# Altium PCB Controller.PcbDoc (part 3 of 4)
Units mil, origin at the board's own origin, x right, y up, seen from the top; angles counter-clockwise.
Board outline 5000 x 8750 mil, 6 copper layers (Top Layer, Layer 1, Layer 2, Layer 3, Layer 4, Bottom Layer), stack 92.6 mil thick; 303 components, 258 nets, 1062 pads, 274 vias.
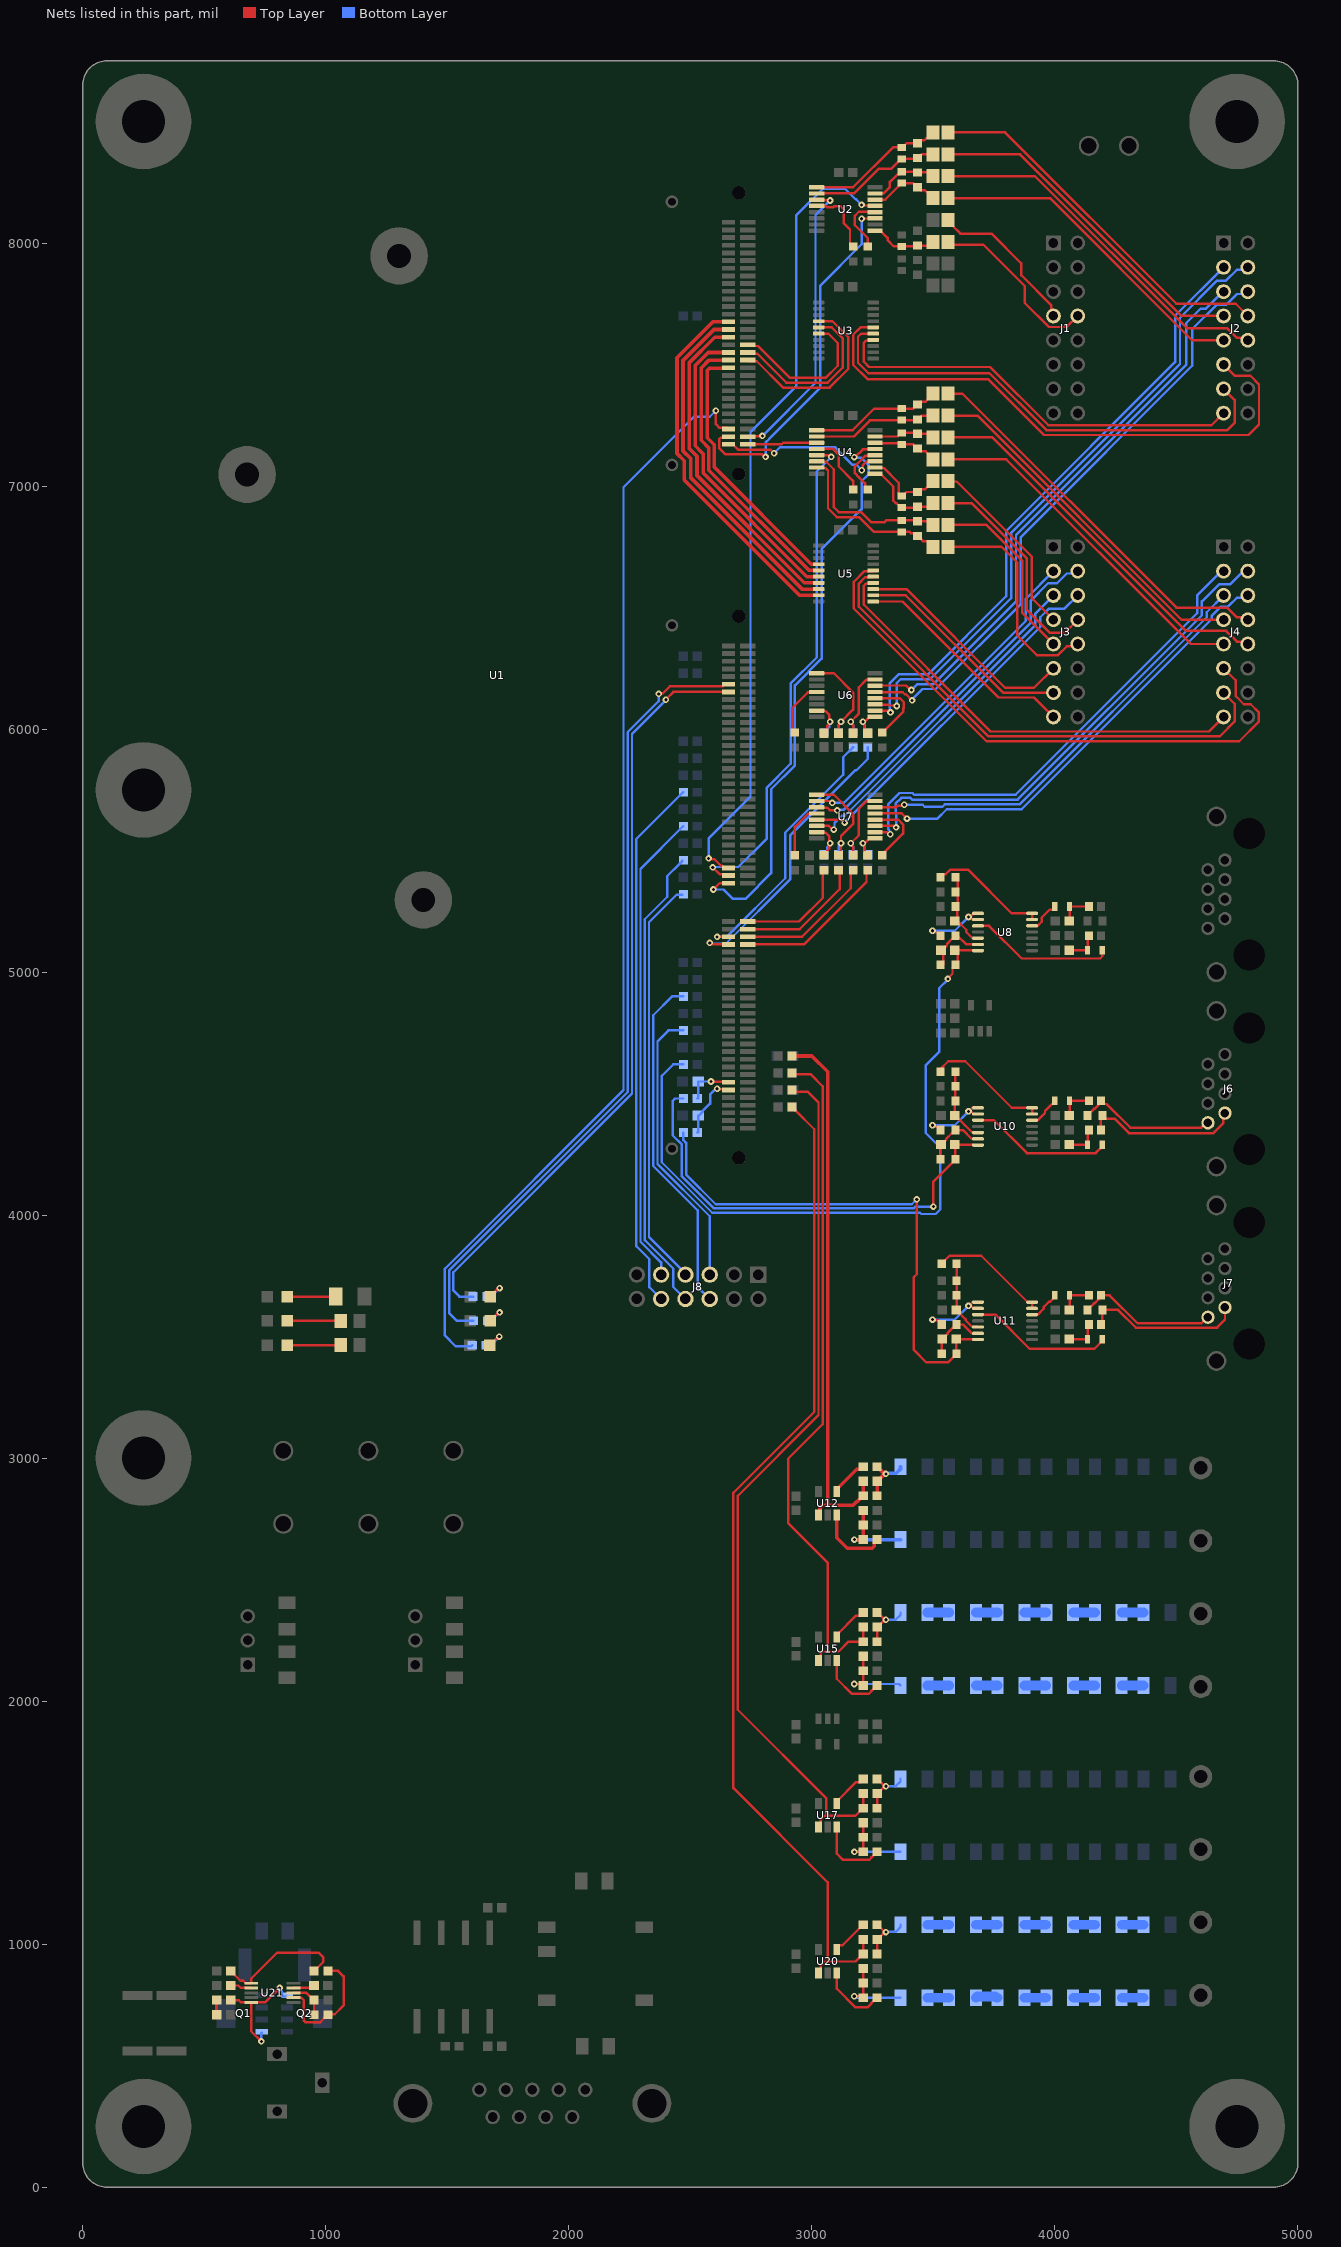
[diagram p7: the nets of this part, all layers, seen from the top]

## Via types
v1: diameter 27, hole 13, Top Layer to Bottom Layer, tented both sides, 274 vias

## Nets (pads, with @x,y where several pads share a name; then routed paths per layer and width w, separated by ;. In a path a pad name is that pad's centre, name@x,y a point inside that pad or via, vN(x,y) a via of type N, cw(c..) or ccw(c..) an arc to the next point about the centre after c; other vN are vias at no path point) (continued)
I_IN: C84.1 R95.2 U1.12 | length 268.7
  Top Layer w10: v1(2610,4520) 2612.32,4517.68 2655.35,4517.68 U1.12@2657.68,4515.35
  Bottom Layer w10: R95.2@2528.62,4340 ccw(c2528.62,4343.93) 2532.55,4343.93 C84.1@2532.55,4410 2535.43,4410 2550.36,4424.92 2550.36,4427.81 2581.5,4458.95 2581.5,4496.81 2601.44,4516.75 2606.75,4516.75 v1(2610,4520)
I_IN_N: J7.7 R51.2 R53.1 | length 660.5
  Top Layer w10: R53.1@4189.63,3550 4195.58,3555.95 R51.2@4195.58,3610 4260,3610 4332.68,3537.32 4667.32,3537.32 4700,3570 J7.7@4700,3620
I_IN_P: J7.8 R48.1 R51.1 | length 582.8
  Top Layer w10: R51.1@4134.42,3610 4134.42,3611.05 4160.47,3637.1 4163.35,3637.1 4177.8,3651.55 4177.8,3658.17 R48.1@4189.63,3670 4225,3670 4340,3555 4602.92,3555 4627.76,3579.84 J7.8@4629.92,3579.84
I_OUT: C81.1 R94.2 U1.14 | length 198.7
  Top Layer w10: v1(2585,4550) 2586.5,4548.5 2656.03,4548.5 U1.14@2657.68,4546.85
  Bottom Layer w10: R94.2@2528.62,4480 ccw(c2528.62,4483.93) 2532.55,4483.93 C81.1@2532.55,4550 v1(2585,4550)
I_OUT_N: J6.7 R40.2 R41.1 | length 652.4
  Top Layer w10: R41.1@4189.63,4350 4189.63,4404.05 R40.2@4195.58,4410 4195.58,4408.95 4207.48,4397.04 4244.67,4397.04 4304.39,4337.32 4652.32,4337.32 4692.48,4377.48 4692.48,4412.48 J6.7@4700,4420
I_OUT_P: J6.8 R36.1 R40.1 | length 579.2
  Top Layer w10: R40.1@4134.42,4410 4134.42,4411.05 4160.47,4437.1 4163.35,4437.1 4177.8,4451.55 4177.8,4458.17 R36.1@4189.63,4470 4189.63,4469.07 4201.46,4457.24 4212.76,4457.24 4310,4360 4601.54,4360 4621.39,4379.84 J6.8@4629.92,4379.84
INA_FLT: U1.121 U4.3 | length 286.2
  Top Layer w10: U1.121@2736.42,7171.78 2876.22,7171.78 2882.83,7178.39 U4.3@3019.92,7178.39
INA_FLT_N: J4.8 L9.1 | length 1618.8
  Top Layer w10: L9.1@3560.55,7380 3620,7380 4500.07,6499.93 4708.53,6499.93 4748.69,6459.76 4784.33,6459.76 J4.8@4794.09,6450
INA_FLT_N_FILT: C7.2 L9.2 R7.1 U4.1 | length 543
  Top Layer w10: U4.1@3019.92,7229.57 3168.03,7229.57 3257.09,7318.62 C7.2@3370,7318.62 3416.99,7318.62 3433.95,7335.58 R7.1@3435,7335.58 3435.58,7335.58 3447.48,7347.48 3468.94,7347.48 3499.45,7378 L9.2@3499.45,7380
INA_FLT_P: J4.7 L10.1 | length 1481.5
  Top Layer w10: L10.1@3560.55,7290 3681.72,7290 4521.72,6450 J4.7@4694.09,6450
INA_FLT_P_FILT: C7.1 L10.2 R7.2 U4.2 | length 515.2
  Top Layer w10: U4.2@3019.92,7203.98 3173.03,7203.98 3239.06,7270 3365.67,7270 3367.05,7271.38 3431.96,7271.38 R7.2@3435,7274.42 3436.05,7274.42 3451.63,7290 L10.2@3499.45,7290
INA_HS: R19.1 U1.49 | length 643.5
  Top Layer w10: U1.49@2736.42,5113.78 2967.69,5113.78 3225,5371.09 R19.1@3225,5419.42
INA_HS_N: J4.4 U7.3 | length 2072.5
  Top Layer w10: U7.3@3260.08,5601.61 3336.16,5601.61 3342.23,5595.54 v1(3346.83,5595.54)
  Bottom Layer w10: v1(3346.83,5595.54) 3346.83,5653.17 3345,5655 3345,5693.5 3368.5,5717 3405.82,5717 3412.82,5710 3846.74,5710 4605,6468.26 4605,6525.27 4675.24,6595.51 4720.51,6595.51 4765.24,6640.24 4784.33,6640.24 J4.4@4794.09,6650
INA_HS_P: J4.3 U7.2 | length 2001.9
  Top Layer w10: U7.2@3260.08,5576.02 3309.58,5576.02
  Bottom Layer w10: v1(3322.79,5567.42) 3319.54,5570.67 3319.54,5582.53 3315,5587.07 3315,5691.78 3360.22,5737 3414.11,5737 3421.11,5730 3838.46,5730 3996.53,5888.07 4585,6476.54 4585,6550 4685,6650 J4.3@4694.09,6650
INA_LEN: J4.13 U5.15 | length 2095.5
  Top Layer w10: U5.15@3252.2,6627.2 3249.49,6624.49 3219.49,6624.49 3193.58,6598.58 3193.58,6503.62 3727.21,5970 4678.46,5970 4739.61,6031.15 4739.61,6104.49 J4.13@4694.09,6150
INA_LEN_CTRL: U1.144 U5.5 | length 1182.2
  Top Layer w15: U1.144@2657.68,7518.24 2577.27,7518.24 2545,7485.97 2545,7187.94 2576.1,7156.83 2576.1,7065.22 2988.31,6653.01 3027.58,6653.01 U5.5@3027.8,6652.8
INA_LS: R18.1 U1.51 | length 589.7
  Top Layer w10: U1.51@2736.42,5145.28 2960,5145.28 3160,5345.28 3160,5414.42 R18.1@3170,5424.42
INA_LS_N: J4.6 U7.5 | length 1931.2
  Top Layer w10: U7.5@3260.08,5652.8 3370.19,5652.8 v1(3391.48,5631.5)
  Bottom Layer w10: v1(3391.48,5631.5) 3516.5,5631.5 3555,5670 3863.31,5670 4645,6451.69 4645,6465.27 4684.22,6504.49 4712.95,6504.49 4748.69,6540.24 4784.33,6540.24 J4.6@4794.09,6550
INA_LS_P: J4.5 U7.6 | length 1814.4
  Top Layer w10: U7.6@3260.08,5678.39 3260.89,5679.19 3346.8,5679.19 3352.86,5685.25 3377.05,5685.25 v1(3380.31,5688.5)
  Bottom Layer w10: v1(3380.31,5688.5) 3456.56,5688.5 3465.06,5680 3536.72,5680 3546.72,5690 3855.03,5690 4625,6459.97 4625,6480.91 J4.5@4694.09,6550
INA_NTC: U1.58 U4.13 | length 2389.3
  Top Layer w10: v1(2595,5340) 2620.75,5365.75 U1.58@2657.68,5365.75 ; v1(3174.4,7119.36) 3178.31,7119.36 3210.01,7151.06 3258.35,7151.06 U4.13@3260.08,7152.8
  Bottom Layer w10: v1(2595,5340) 2636.45,5340 2674.95,5301.5 2726.5,5301.5 2832.5,5407.5 2832.5,5752.5 2930,5850 2930,6180 3040,6290 3040,6740.31 3205,6905.31 3205,7020 3235,7050 3235,7085 3202.9,7117.1 3176.66,7117.1 v1(3174.4,7119.36)
INA_NTC_N: J4.10 L11.1 | length 1585.6
  Top Layer w10: L11.1@3560.55,7200 3743.43,7200 4539.6,6403.83 4704.62,6403.83 4748.69,6359.76 4784.33,6359.76 J4.10@4794.09,6350
INA_NTC_N_FILT: C9.2 L11.2 R8.1 U4.15 | length 253.2
  Top Layer w10: U4.15@3260.08,7203.98 3352.4,7203.98 3367.05,7218.62 C9.2@3370,7218.62 3431.96,7218.62 R8.1@3435,7215.58 3483.87,7215.58 L11.2@3499.45,7200
INA_NTC_P: J4.9 L12.1 | length 1448.4
  Top Layer w10: L12.1@3560.55,7110 3800,7110 4560,6350 J4.9@4694.09,6350
INA_NTC_P_FILT: C9.1 L12.2 R8.2 U4.14 | length 268.9
  Top Layer w10: U4.14@3260.08,7178.39 3261.81,7176.65 3364.72,7176.65 C9.1@3370,7171.38 3416.99,7171.38 3433.95,7154.42 R8.2@3435,7154.42 3446.9,7142.52 3468.94,7142.52 3499.45,7112 L12.2@3499.45,7110
INA_OCEN: J4.15 U5.14 | length 1842.5
  Top Layer w10: U5.14@3252.2,6601.61 3249.49,6598.9 3223.52,6598.9 3213.58,6588.96 3213.58,6511.91 3735.49,5990 4634.09,5990 J4.15@4694.09,6050
INA_OCEN_CTRL: U1.146 U5.6 | length 1268
  Top Layer w15: U1.146@2657.68,7549.73 2573.41,7549.73 2520,7496.32 2520,7166.01 2545.5,7140.5 2545.5,7139.85 2552.5,7132.86 2552.5,7082.76 2552.63,7082.63 2552.63,7053.34 2978.76,6627.2 U5.6@3027.8,6627.2
INA_PSDIS: J4.11 U5.16 | length 2431.5
  Top Layer w10: U5.16@3252.2,6652.8 3249.49,6650.08 3216.79,6650.08 3172.5,6605.78 3172.5,6496.42 3718.92,5950 4758.46,5950 4839.61,6031.15 4839.61,6068.85 4806.19,6102.27 4777.46,6102.27 4744.04,6135.69 4744.04,6200.06 J4.11@4694.09,6250
INA_PSDIS_CTRL: U1.142 U5.4 | length 1096.4
  Top Layer w15: U1.142@2657.68,7486.74 2655.33,7484.4 2578.79,7484.4 2570,7475.61 2570,7198.29 2598.6,7169.69 2598.6,7078.08 2998.08,6678.6 3027.58,6678.6 U5.4@3027.8,6678.39
INB_FLT: U1.122 U4.11 | length 693.3
  Top Layer w10: U1.122@2657.68,7171.78 2674.41,7171.78 2696.19,7150 2698.2,7150 2698.76,7149.44 2830.56,7149.44 v1(2845,7135) ; v1(3205.4,7065.1) 3208.65,7068.35 3208.65,7085.03 3223.51,7099.88 3258.35,7099.88 U4.11@3260.08,7101.61
  Bottom Layer w10: v1(2845,7135) 2870,7160 3095.31,7160 3107.44,7147.86 3107.44,7146.01 3165.5,7087.95 3182.55,7087.95 v1(3205.4,7065.1)
INB_FLT_N: J3.8 L14.1 | length 901.2
  Top Layer w10: L14.1@3560.55,6930 3656.72,6930 3885,6701.72 3885,6490.51 3980,6395.51 4039.61,6395.51 J3.8@4094.09,6450
INB_FLT_N_FILT: C10.2 L14.2 R11.1 U4.9 | length 338.8
  Top Layer w10: U4.9@3260.08,7050.43 3282.72,7050.43 3335,6998.15 3335,6939.93 3346.07,6928.86 3349.57,6928.86 3367.05,6911.38 C10.2@3370,6911.38 3431.96,6911.38 R11.1@3435,6914.42 3483.87,6914.42 L14.2@3499.45,6930
INB_FLT_P: J3.7 L13.1 | length 769.8
  Top Layer w10: L13.1@3560.55,7020 3561.9,7018.65 3596.35,7018.65 3905,6710 3905,6539.09 J3.7@3994.09,6450
INB_FLT_P_FILT: C10.1 L13.2 R11.2 U4.10 | length 341.1
  Top Layer w10: U4.10@3260.08,7076.02 3261.81,7074.29 3296.65,7074.29 3357.28,7013.65 3357.28,6968.39 3367.05,6958.62 C10.1@3370,6958.62 3372.95,6958.62 3389.91,6975.58 R11.2@3435,6975.58 3446.9,6987.48 3466.94,6987.48 3475.79,6996.33 3477.79,6996.33 3499.45,7018 L13.2@3499.45,7020
INB_HS: R17.1 U1.53 | length 531.6
  Top Layer w10: U1.53@2736.42,5176.77 2950,5176.77 3115,5341.77 3115,5419.42 R17.1@3110,5424.42
INB_HS_N: J3.4 U7.11 | length 1540.8
  Top Layer w10: U7.11@3019.92,5678.39 3021.65,5676.65 3063.4,5676.65 3074.79,5665.26 v1(3104.78,5665.26)
  Bottom Layer w10: v1(3104.78,5665.26) 3108.04,5668.51 3131.94,5668.51 3900,6436.57 3900,6527.62 3972.38,6600 4008.46,6600 4048.69,6640.24 4084.33,6640.24 J3.4@4094.09,6650
INB_HS_P: J3.3 U7.10 | length 1425.9
  Top Layer w10: U7.10@3019.92,5703.98 3071.78,5703.98 3079.69,5696.06 v1(3084.29,5696.06)
  Bottom Layer w10: v1(3084.29,5696.06) 3131.21,5696.06 3880,6444.85 3880,6535.91 J3.3@3994.09,6650
INB_LEN: J3.13 U5.12 | length 907.8
  Top Layer w10: U5.12@3252.2,6550.43 3386.14,6550.43 3786.57,6150 J3.13@3994.09,6150
INB_LEN_CTRL: U1.152 U5.8 | length 1452.6
  Top Layer w15: U1.152@2657.68,7644.22 2597.19,7644.22 2470,7517.03 2470,7144.64 2502.32,7112.32 2502.32,7032.94 2959.24,6576.02 U5.8@3027.8,6576.02
INB_LS: R16.1 U1.55 | length 469.9
  Top Layer w10: U1.55@2736.42,5208.27 2947.8,5208.27 3045,5305.47 3045,5419.42 R16.1@3050,5424.42
INB_LS_N: J3.6 U7.13 | length 1490.1
  Top Layer w10: U7.13@3019.92,5627.2 3118.19,5627.2 3130.4,5615 v1(3135,5615)
  Bottom Layer w10: v1(3135,5615) 3940,6420 3940,6460.27 3975.24,6495.51 4039.61,6495.51 J3.6@4094.09,6550
INB_LS_P: J3.5 U7.14 | length 1421.4
  Top Layer w10: U7.14@3019.92,5601.61 3070.29,5601.61 3085.4,5586.5 v1(3090,5586.5)
  Bottom Layer w10: v1(3090,5586.5) 3093.25,5589.75 3093.25,5613.56 3123.19,5643.5 3135.22,5643.5 3920,6428.28 3920,6475 3994.09,6549.09 J3.5@3994.09,6550
INB_NTC: U1.60 U4.5 | length 2093.9
  Top Layer w10: v1(2592.45,5431) 2621.37,5402.09 2652.83,5402.09 U1.60@2657.68,5397.24 ; U4.5@3019.92,7127.2 3068.2,7127.2 3075.4,7120 v1(3080,7120)
  Bottom Layer w10: v1(2592.45,5431) 2593.93,5432.48 2697.48,5432.48 2815,5550 2815,5759.75 2912.5,5857.25 2912.5,6187.5 3020,6295 3020,7060 v1(3080,7120)
INB_NTC_N: J3.10 L16.1 | length 912.8
  Top Layer w10: L16.1@3560.55,6750 3780.15,6750 3845,6685.15 3845,6385 3925.51,6304.49 4012.95,6304.49 4048.69,6340.24 4084.33,6340.24 J3.10@4094.09,6350
INB_NTC_N_FILT: C11.2 L16.2 R12.1 U4.7 | length 707
  Top Layer w10: U4.7@3019.92,7076.02 3021.65,7074.29 3056.49,7074.29 3066.42,7064.36 3066.42,6908.58 3102.48,6872.52 3194.2,6872.52 3255.34,6811.38 C11.2@3370,6811.38 3402.72,6811.38 3407.77,6806.32 3423.1,6806.32 R12.1@3435,6794.42 3436.05,6794.42 3456.81,6773.67 3477.79,6773.67 3499.45,6752 L16.2@3499.45,6750
INB_NTC_P: J3.9 L15.1 | length 762.1
  Top Layer w10: L15.1@3560.55,6840 3718.43,6840 3865,6693.43 3865,6479.09 J3.9@3994.09,6350
INB_NTC_P_FILT: C11.1 L15.2 R12.2 U4.6 | length 685.1
  Top Layer w10: U4.6@3019.92,7101.61 3021.65,7099.88 3059.18,7099.88 3090,7069.06 3090,6913.28 3110.77,6892.52 3202.48,6892.52 3243.5,6851.5 3299.18,6851.5 3306.3,6858.62 3431.96,6858.62 R12.2@3435,6855.58 3483.87,6855.58 L15.2@3499.45,6840
INB_OCEN: J3.15 U5.11 | length 938.6
  Top Layer w10: U5.11@3252.2,6524.84 3372.95,6524.84 3767.8,6130 3914.09,6130 J3.15@3994.09,6050
INB_OCEN_CTRL: U1.154 U5.9 | length 1538.4
  Top Layer w15: U1.154@2657.68,7675.72 2593.33,7675.72 2445,7527.39 2445,7134.29 2474.64,7104.64 2474.64,7025.26 2949.47,6550.43 U5.9@3027.8,6550.43
INB_PSDIS: J3.11 U5.13 | length 943.2
  Top Layer w10: U5.13@3252.2,6576.02 3388.83,6576.02 3794.85,6170 3914.09,6170 J3.11@3994.09,6250
INB_PSDIS_CTRL: U1.150 U5.7 | length 1366.8
  Top Layer w15: U1.150@2657.68,7612.72 2601.05,7612.72 2495,7506.68 2495,7155 2527.5,7122.5 2527.5,7043.11 2969,6601.61 U5.7@3027.8,6601.61
LED_G: R96.2 U1.108 | length 3157.3
  Top Layer w10: v1(2399.68,6120.57) 2399.68,6122.68 2430.16,6153.15 U1.108@2657.68,6153.15
  Bottom Layer w10: R96.2@1606.38,3665 1550,3665 1525,3690 1525,3765 2260,4500 2260,5980 2399.68,6119.68 v1(2399.68,6120.57)
LED_R: R98.2 U1.126 | length 4554.5
  Top Layer w10: v1(2605,7310) 2605,7255 2620.39,7239.61 2652.83,7239.61 U1.126@2657.68,7234.77
  Bottom Layer w10: R98.2@1602.76,3465 1597.76,3460 1535,3460 1490,3505 1490,3779.5 2225,4514.5 2225,6995.13 2514.87,7285 2580,7285 v1(2605,7310)
LED_Y: R97.2 U1.110 | length 3322.6
  Top Layer w10: v1(2370,6145) 2372.65,6147.65 2387.65,6147.65 2415.49,6175.49 2631.79,6175.49 2640.94,6184.65 U1.110@2657.68,6184.65
  Bottom Layer w10: R97.2@1607.76,3565 1540,3565 1507.5,3597.5 1507.5,3772.25 2242.5,4507.25 2242.5,5987.5 2370,6115 v1(2370,6145)
NetC14_1: C14.1 R86.2 U6.15 | length 201.4
  Top Layer w10: U6.15@3019.92,6076.02 3021.65,6074.29 3056.49,6074.29 3072.28,6058.5 3072.28,6032.72 v1(3075,6030) 3075,6025.4 3063.86,6014.26 3063.86,5997.44 C14.1@3050,5983.58
  Bottom Layer w10: R86.2@3050,5985.58 3051.05,5985.58 3062.96,5997.48 3062.96,5998.53 3071.75,6007.33 3071.75,6026.75 v1(3075,6030)
NetC15_1: C15.1 R85.2 U6.9 | length 423.3
  Top Layer w10: U6.9@3019.92,6229.57 3091.09,6229.57 3170,6150.66 3170,6080 v1(3120,6030) 3120,6026.29 3110,6016.29 C15.1@3110,5983.58
  Bottom Layer w10: R85.2@3110,5985.58 3110,6016.29 3120,6026.29 v1(3120,6030)
NetC16_1: C16.1 R84.2 U6.7 | length 334.5
  Top Layer w10: v1@3160,6030 3193.38,6063.38 3193.38,6172.11 3223.51,6202.24 3258.35,6202.24 U6.7@3260.08,6203.98 ; v1(3160.15,6029.85) 3160.15,6026.14 3170,6016.29 C16.1@3170,5983.58
  Bottom Layer w10: v1(3160.15,6029.85) 3160.15,6026.14 3170,6016.29 R84.2@3170,5985.58
NetC17_1: C17.1 R83.2 U6.1 | length 152
  Top Layer w10: C17.1@3230,5983.58 3216.14,5997.44 3216.14,6019.26 3210,6025.4 v1(3210,6030) 3213.25,6033.25 3220.26,6033.25 3237.44,6050.43 U6.1@3260.08,6050.43
  Bottom Layer w10: 3217.04,6018.36 3217.04,5997.48 3228.95,5985.58 R83.2@3230,5985.58
NetC19_1: C19.1 R21.2 R22.1 R24.2 U8.12 | length 300.8
  Top Layer w10: R21.2@3600.58,5390 3600.58,5330 3600.58,5270 3598.58,5268 3598.58,5210 3599.53,5210 3635.19,5174.33 3635.19,5164.91 3659.97,5140.13 3683.06,5140.13 U8.12@3683.78,5139.41
NetC20_1: C20.1 R23.2 R25.1 | length 140.7
  Top Layer w10: C20.1@4058.58,5210 4060.51,5211.93 R25.1@4060.51,5270 R23.2@4140.37,5270
NetC22_1: C22.1 R28.2 R30.1 U8.13 | length 251.3
  Top Layer w10: R30.1@3539.42,5030 3541.42,5032 3541.42,5099.05 3546.24,5103.86 3550.41,5103.86 3556.26,5109.72 3556.26,5116.26 3577.04,5137.04 3588.68,5137.04 3600.58,5148.95 3635.71,5113.82 U8.13@3683.78,5113.82
NetC22_2: C22.2 R30.2 R93.1 U8.14 | length 2934.9
  Top Layer w10: v1(3560.08,4972.32) 3560.08,4974.68 3578.68,4993.28 3578.68,5018.1 R30.2@3590.58,5030 ; R30.2@3600.58,5030 3600.58,5088 3598.58,5090 3663.27,5090 3665.04,5088.23 U8.14@3683.78,5088.23
  Bottom Layer w10: R93.1@2471.38,4620 2429.69,4620 2382.5,4572.81 2382.5,4217.5 2590,4010 3445,4010 3450.25,4004.75 3510.06,4004.75 3528.5,4023.19 3528.5,4278.4 3468,4338.9 3468,4615.8 3523.5,4671.3 3523.5,4933.5 3560.08,4970.08 v1(3560.08,4972.32)
NetC23_1: C23.1 R27.2 R29.1 | length 138.3
  Top Layer w10: C23.1@4058.58,5090 R29.1@4134.49,5090 4134.49,5144.12 R27.2@4140.37,5150
NetC27_1: C27.1 R33.2 R34.1 R37.2 U10.12 | length 315.3
  Top Layer w10: R33.2@3590.58,4600 R34.1@3590.58,4530 R37.2@3590.58,4470 3588.58,4468 C27.1@3588.58,4410 3589.53,4410 3629.53,4370 3630.11,4370 3659.97,4340.13 3683.06,4340.13 U10.12@3683.78,4339.41
NetC28_1: C28.1 R36.2 R38.1 | length 140.7
  Top Layer w10: C28.1@4058.58,4410 4060.51,4411.93 R38.1@4060.51,4470 R36.2@4140.37,4470
NetC30_1: C30.1 R42.2 R44.1 U10.13 | length 255.8
  Top Layer w10: R44.1@3529.42,4230 3529.42,4288 C30.1@3531.42,4290 3532.37,4290 3553.76,4311.39 3553.76,4315.08 3575.73,4337.04 3578.68,4337.04 3590.58,4348.95 R42.2@3590.58,4350 3621.82,4350 3657.28,4314.54 3683.06,4314.54 U10.13@3683.78,4313.82
NetC30_2: C30.2 R44.2 R94.1 U10.14 | length 1856
  Top Layer w10: v1(3500,4035) 3500,4138.37 3590.58,4228.95 3590.58,4288 C30.2@3588.58,4290 3663.27,4290 3665.04,4288.23 U10.14@3683.78,4288.23
  Bottom Layer w10: R94.1@2471.38,4480 2437.52,4480 2427.5,4469.98 2427.5,4328.04 2465.35,4290.19 2465.35,4159.39 2597.25,4027.5 3418.44,4027.5 3425.94,4035 v1(3500,4035)
NetC31_1: C31.1 R41.2 R43.1 | length 138.3
  Top Layer w10: C31.1@4058.58,4290 R43.1@4134.49,4290 4134.49,4344.12 R41.2@4140.37,4350
NetC32_1: C32.1 R45.2 R46.1 R49.2 U11.12 | length 312.9
  Top Layer w10: R45.2@3595.58,3800 R46.1@3595.58,3730 R49.2@3595.58,3670 3595.58,3612 C32.1@3593.58,3610 3594.53,3610 3632.69,3571.83 3632.69,3567.41 3659.97,3540.13 3683.06,3540.13 U11.12@3683.78,3539.41
NetC33_1: C33.1 R48.2 R50.1 | length 140.7
  Top Layer w10: C33.1@4058.58,3610 4060.51,3611.93 R50.1@4060.51,3670 R48.2@4140.37,3670
NetC35_1: C35.1 R54.2 R57.1 U11.13 | length 250.8
  Top Layer w10: R57.1@3534.42,3430 3534.42,3488 C35.1@3536.42,3490 3537.37,3490 3558.76,3511.39 3558.76,3515.08 3580.73,3537.04 3583.68,3537.04 3595.58,3548.95 R54.2@3595.58,3550 3621.82,3550 3657.28,3514.54 3683.06,3514.54 U11.13@3683.78,3513.82
NetC35_2: C35.2 R57.2 R95.1 U11.14 | length 2174.1
  Top Layer w10: v1(3431.5,4065) 3431.5,3756.7 3420,3745.2 3420,3445 3470.86,3394.14 3560.77,3394.14 3595.58,3428.95 R57.2@3595.58,3430 3593.58,3432 C35.2@3593.58,3490 3663.27,3490 3665.04,3488.23 U11.14@3683.78,3488.23
  Bottom Layer w10: R95.1@2471.38,4340 2471.38,4308.91 2482.85,4297.44 2482.85,4166.64 2604.5,4045 3411.19,4045 3431.19,4065 v1(3431.5,4065)
NetC36_1: C36.1 R53.2 R55.1 | length 138.3
  Top Layer w10: C36.1@4058.58,3490 R55.1@4134.49,3490 4134.49,3544.12 R53.2@4140.37,3550
NetC37_1: C37.1 R58.1 R59.1 R104.2 | length 235.7
  Top Layer w15: R59.1@3268.62,2845 C37.1@3268.58,2905 3269.51,2904.98 3297.23,2932.7 3302.7,2932.7 v1(3305,2935) 3302,2935 3295.64,2941.36 3293.16,2941.36 3269.53,2965 R58.1@3268.62,2965
  Bottom Layer w15: v1(3305,2935) 3307.3,2937.3 3337.18,2937.3 3337.93,2938.05 3347.78,2938.05 3364.88,2955.16 R104.2@3364.88,2965
NetC37_2: C37.2 R31.1 R59.2 U12.1 | length 2246.5
  Top Layer w15: R31.1@2918.62,4655 3000,4655 3065,4590 3065,2806.91 ; U12.1@3027.6,2766.77 3033.72,2772.89 3033.72,2796.66 3043.97,2806.91 3065,2806.91 ; C37.2@3211.42,2905 R59.2@3211.38,2845 3210.47,2845 3186.84,2821.36 3184.36,2821.36 3169.91,2806.91 3065,2806.91
NetC39_1: C39.1 R60.2 R61.1 R110.2 | length 346.3
  Top Layer w15: v1(3175,2665) R61.1@3211.38,2665 R60.2@3211.38,2725 C39.1@3211.42,2785
  Bottom Layer w15: v1(3175,2665) R110.2@3364.88,2665
NetC42_1: C42.1 R62.1 R63.2 R116.2 | length 235.7
  Top Layer w10: R63.2@3268.62,2245 R63.2@3268.62,2245 C42.1@3268.58,2305 3269.53,2305 3296.27,2331.75 3301.75,2331.75 v1(3305,2335) 3301.75,2338.25 3296.27,2338.25 3269.53,2365 R62.1@3268.62,2365
  Bottom Layer w10: v1(3305,2335) 3305.55,2335.55 3345.28,2335.55 3364.88,2355.16 R116.2@3364.88,2365
NetC42_2: C42.2 R32.1 R63.1 U15.1 | length 2889.1
  Top Layer w10: R32.1@2918.62,4585 2923.62,4580 2995,4580 3045,4530 3045,3140 2902.5,2997.5 2902.5,2732.5 3065,2570 3065,2204.41 ; U15.1@3027.6,2166.77 3036.22,2175.39 3036.22,2195.62 3045.01,2204.41 3065,2204.41 ; C42.2@3211.42,2305 C42.2@3211.42,2305 R63.1@3211.38,2245 3151.55,2245 3110.96,2204.41 3065,2204.41
NetC46_1: C46.1 R64.1 R65.1 R122.2 | length 352.4
  Top Layer w10: v1(3174.35,2070.84) 3205.54,2070.84 R65.1@3211.38,2065 R64.1@3211.38,2125 R64.1@3211.38,2125 C46.1@3211.42,2185
  Bottom Layer w10: v1(3174.35,2070.84) 3359.04,2070.84 R122.2@3364.88,2065
NetC50_1: C50.1 R66.1 R67.1 R128.2 | length 235.7
  Top Layer w10: R67.1@3268.62,1560 R67.1@3268.62,1560 C50.1@3268.58,1620 3269.53,1620 3296.27,1646.75 3301.75,1646.75 v1(3305,1650) 3301.75,1653.25 3296.27,1653.25 3269.53,1680 R66.1@3268.62,1680
  Bottom Layer w10: v1(3305,1650) 3305.55,1650.55 3345.28,1650.55 3364.88,1670.16 R128.2@3364.88,1680
NetC50_2: C50.2 R35.1 R67.2 U17.1 | length 3641.4
  Top Layer w10: R35.1@2918.62,4515 2925.12,4508.5 2981.81,4508.5 3027.5,4462.81 3027.5,3177.5 2695,2845 2695,1965 3060,1600 3060,1528.83 ; U17.1@3027.6,1481.77 3036.22,1490.39 3036.22,1510.62 3054.43,1528.83 3060,1528.83 ; C50.2@3211.42,1620 R67.2@3211.38,1560 R67.2@3211.38,1560 3210.47,1560 3179.31,1528.83 3060,1528.83
NetC52_1: C52.1 R68.2 R69.1 R134.2 | length 346.3
  Top Layer w10: v1(3175,1380) R69.1@3211.38,1380 R68.2@3211.38,1440 C52.1@3211.42,1500 C52.1@3211.42,1500
  Bottom Layer w10: v1(3175,1380) R134.2@3364.88,1380
NetC55_1: C55.1 R70.1 R71.2 R140.2 | length 235.7
  Top Layer w10: R71.2@3268.62,960 C55.1@3268.58,1020 C55.1@3268.58,1020 3269.53,1020 3296.27,1046.75 3301.75,1046.75 v1(3305,1050) 3301.75,1053.25 3296.27,1053.25 3269.53,1080 R70.1@3268.62,1080
  Bottom Layer w10: v1(3305,1050) 3305.55,1050.55 3345.28,1050.55 3364.88,1070.16 R140.2@3364.88,1080
NetC55_2: C55.2 R39.1 R71.1 U20.1 | length 4140.8
  Top Layer w10: R39.1@2918.62,4445 2919.53,4445 2932.48,4432.04 2932.48,4431.14 3010,4353.62 3010,3190 2677.5,2857.5 2677.5,1642.5 3065,1255 3065,928.83 ; U20.1@3027.6,881.77 3036.22,890.39 3036.22,910.62 3054.43,928.83 3065,928.83 ; C55.2@3211.42,1020 R71.1@3211.38,960 R71.1@3211.38,960 3210.47,960 3179.31,928.83 3065,928.83
NetC57_1: C57.1 R74.1 R76.1 R147.2 | length 352.4
  Top Layer w10: v1(3174.35,785.84) 3205.54,785.84 R76.1@3211.38,780 R74.1@3211.38,840 C57.1@3211.42,900 C57.1@3211.42,900
  Bottom Layer w10: v1(3174.35,785.84) 3178.95,785.84 3184.79,780 R147.2@3364.88,780
NetC58_1: C58.1 U21.4 | length 89.6
  Top Layer w10: U21.4@867.09,819.68 867.99,820.59 942.01,820.59 C58.1@951.42,830 ; C58.1@950.47,835 C58.1@951.42,835
NetC59_1: C59.1 R79.1 | length 60
  Top Layer w10: R79.1@550,770 550,710.09 C59.1@550.09,710
NetC65_1: C70.1 R19.2 U7.1 | length 140.4
  Top Layer w10: 3217.04,5518.36 3217.04,5497.48 3228.95,5485.58 R19.2@3230,5485.58 ; v1@3220.26,5533.25 3237.44,5550.43 U7.1@3260.08,5550.43
  Bottom Layer w10: v1(3210,5530) 3210,5525.4 3216.14,5519.26 3216.14,5497.44 C70.1@3230,5483.58
NetC66_1: C71.1 R18.2 U7.7 | length 335
  Top Layer w10: R18.2@3170,5485.58 3170,5516.29 3160,5526.29 v1(3160,5530) 3193.38,5563.38 3193.38,5672.11 3223.51,5702.24 3258.35,5702.24 U7.7@3260.08,5703.98
  Bottom Layer w10: v1(3160,5530) 3160,5526.29 3170,5516.29 C71.1@3170,5483.58
NetC67_1: C72.1 R17.2 U7.9 | length 423.3
  Top Layer w10: U7.9@3019.92,5729.57 3091.09,5729.57 3170,5650.66 3170,5609.69 3120,5559.69 v1(3120,5530) 3120,5495.58 R17.2@3110,5485.58
  Bottom Layer w10: C72.1@3110,5483.58 3110,5516.29 3120,5526.29 v1(3120,5530)
NetC68_1: C73.1 R16.2 U7.15 | length 201.4
  Top Layer w10: U7.15@3019.92,5576.02 3021.65,5574.29 3056.49,5574.29 3072.28,5558.5 3072.28,5532.72 v1(3075,5530) 3071.75,5526.75 3071.75,5507.33 3062.96,5498.53 3062.96,5497.48 3051.05,5485.58 R16.2@3050,5485.58
  Bottom Layer w10: C73.1@3050,5483.58 3063.86,5497.44 3063.86,5514.26 3075,5525.4 v1(3075,5530)
NetD1_2: D1.2 R47.2 | length 199.6
  Top Layer w10: D1.2@841.34,3665 R47.2@1040.9,3665
NetD2_2: D2.2 R96.1 | length 119
  Top Layer w10: D2.2@1676.34,3665 1711.34,3700 v1(1715,3700)
  Bottom Layer w10: R96.1@1663.62,3665 1676.58,3677.96 1692.96,3677.96 v1(1715,3700)
NetD3_2: D3.2 R52.1 | length 220.2
  Top Layer w10: D3.2@841.34,3565 R52.1@1061.54,3565
NetD4_2: D4.2 R97.1 | length 117.7
  Top Layer w10: D4.2@1676.34,3565 1711.34,3600 v1(1715,3600)
  Bottom Layer w10: R97.1@1665,3565 1677.96,3577.96 1692.96,3577.96 v1(1715,3600)
NetD5_2: D5.2 R56.1 | length 216.7
  Top Layer w10: D5.2@841.34,3465 R56.1@1058.07,3465
NetD6_2: D6.2 R98.1 | length 121.3
  Top Layer w10: D6.2@1675,3465 1710,3500 v1(1713.66,3500)
  Bottom Layer w10: R98.1@1660,3465 1672.96,3477.96 1691.62,3477.96 v1(1713.66,3500)
NetJ8_5: J8.5 R92.1 | length 1174.1
  Bottom Layer w10: R92.1@2471.38,4760 2410,4760 2365,4715 2365,4210.25 2580,3995.25 J8.5@2580,3755
NetJ8_6: J8.6 R91.1 | length 1419.8
  Bottom Layer w10: R91.1@2471.38,4900 2425,4900 2347.5,4822.5 2347.5,4202.5 2530,4020 2530,3705 J8.6@2580,3655
NetJ8_7: J8.7 R90.1 | length 1695.3
  Bottom Layer w10: R90.1@2466.2,5318.38 2443.38,5318.38 2330,5205 2330,3909.75 2480,3759.75 J8.7@2480,3755
NetJ8_8: J8.8 R89.1 | length 1936.3
  Bottom Layer w10: R89.1@2467.47,5457.47 2467.47,5457 2457.52,5447.04 2457.04,5447.04 2405,5395 2405,5310 2312.5,5217.5 2312.5,3897.5 2430,3780 2430,3705 J8.8@2480,3655
NetJ8_9: J8.9 R88.1 | length 1953.8
  Bottom Layer w10: J8.9@2380,3755 2380,3805.25 2295,3890.25 2295,5424.53 2470.47,5600 R88.1@2471.38,5600
NetJ8_10: J8.10 R87.1 | length 2208.3
  Bottom Layer w10: J8.10@2380,3655 2331.54,3703.46 2331.54,3818.46 2277.5,3872.5 2277.5,5547.03 2470.47,5740 R87.1@2471.38,5740
NetQ1_4: Q1.4 Q2.4 R79.2 U21.10 | length 500.9
  Top Layer w10: R79.2@607.24,770 641.25,770 649.86,761.39 692.15,761.39 U21.10@692.91,760.63 ; U21.10@691.63,760.63 691.63,760.02 U21.10@691.92,759.73 ; v1(735,600) 692.91,642.09 U21.10@692.91,760.63 ; v1(810,820) 750.63,760.63 U21.10@692.91,760.63
  Bottom Layer w10: v1(735,600) 735,633.54 Q1.4@736.46,635 ; v1(810,820) 810,815.4 819.88,805.52 819.88,792.01 826.89,785 Q2.4@839.88,785
NetR4_1: R4.1 U2.4 | length 291.3
  Top Layer w10: U2.4@3019.92,8152.8 3021.65,8151.06 3058.63,8151.06 3063.19,8146.5 3086.81,8146.5 3091.92,8151.61 3118.46,8151.61 3131.88,8138.19 3131.88,8080.42 3157.04,8055.25 3157.04,7997.48 3168.95,7985.58 R4.1@3170,7985.58
NetR5_2: R5.2 U2.12 | length 239.4
  Top Layer w10: R5.2@3230,7985.58 3230,8020.09 3176.5,8073.59 3176.5,8111.81 3193.19,8128.5 3258.78,8128.5 U2.12@3260.08,8127.2
NetR9_1: R9.1 U4.4 | length 269
  Top Layer w10: U4.4@3019.92,7152.8 3087.51,7152.8 3110,7130.31 3110,7081.24 3170,7021.24 R9.1@3170,6985.58
NetR10_2: R10.2 U4.12 | length 220.1
  Top Layer w10: R10.2@3230,6985.58 3219.27,6996.31 3219.27,7010.92 3194.81,7035.39 3176.9,7053.29 3176.9,7081.56 3188.65,7093.31 3220.82,7125.47 3258.35,7125.47 U4.12@3260.08,7127.2
NetR13_2: R13.2 U6.12 | length 233.2
  Top Layer w10: R13.2@2930,5985.58 2920,5995.58 2920,6087.71 2983.35,6151.06 3018.19,6151.06 U6.12@3019.92,6152.8
NetR14_1: R14.1 U6.4 | length 287.5
  Top Layer w10: U6.4@3260.08,6127.2 3361.81,6127.2 3378.5,6110.51 3378.5,6086.9 3375.8,6084.2 3375.8,6070.33 3291.05,5985.58 R14.1@3290,5985.58
NetR15_2: R15.2 U7.12 | length 229.9
  Top Layer w10: R15.2@2930,5480.58 2930,5597.71 2983.35,5651.06 3018.19,5651.06 U7.12@3019.92,5652.8
NetR20_1: R20.1 U7.4 | length 281.2
  Top Layer w10: U7.4@3260.08,5627.2 3355.47,5627.2 3375.33,5607.34 3375.33,5569.86 3291.05,5485.58 R20.1@3290,5485.58
NetR21_1: R21.1 U8.6 U8.7 | length 489.6
  Top Layer w10: R21.1@3529.42,5390 3529.42,5391.05 3541.32,5402.96 3551,5402.96 3568.5,5420.46 3644.02,5420.46 3822.7,5241.77 U8.7@3906.22,5241.77 U8.6@3906.22,5216.18
NetR25_2: R25.2 U8.5 | length 140.3
  Top Layer w10: U8.5@3906.22,5190.59 3906.94,5191.31 3930.03,5191.31 3945.83,5207.11 3945.83,5224.29 3978.82,5257.28 3993.66,5257.28 3999.49,5263.11 R25.2@3999.49,5270
NetR28_1: R28.1 U8.8 U8.9 | length 310.7
  Top Layer w10: v1(3496.5,5170) 3501.1,5170 3508.15,5162.96 3526.47,5162.96 R28.1@3539.42,5150 ; v1(3644.69,5226.75) v1@3645.67,5226.75 ; U8.9@3683.78,5216.18 3665.04,5216.18 3664.32,5216.9 3659.13,5216.9 3649.29,5226.75 v1@3645.67,5226.75 ; U8.8@3683.78,5241.77 3665.04,5241.77 3656.52,5233.25 3652.18,5233.25 v1@3645.67,5226.75
  Bottom Layer w10: v1(3496.5,5170) 3587.94,5170 v1(3644.69,5226.75)
NetR29_2: R29.2 U8.10 | length 595.8
  Top Layer w10: U8.10@3683.78,5190.59 3684.07,5190.3 3729.7,5190.3 3863.86,5056.14 4186.14,5056.14 4195,5065 4195,5089.49 R29.2@4195.51,5090
NetR33_1: R33.1 U10.6 U10.7 | length 495.8
  Top Layer w10: R33.1@3529.42,4600 3529.42,4601.05 3561.32,4632.96 3631.52,4632.96 3822.7,4441.77 U10.7@3906.22,4441.77 U10.6@3906.22,4416.18
NetR38_2: R38.2 U10.5 | length 134.4
  Top Layer w10: U10.5@3906.22,4390.59 3906.94,4391.31 3930.03,4391.31 3959.42,4420.71 3959.42,4427.89 3988.82,4457.28 3993.66,4457.28 3999.49,4463.11 R38.2@3999.49,4470
NetR42_1: R42.1 U10.8 U10.9 | length 302.3
  Top Layer w10: v1(3496.5,4370) 3501.1,4370 3508.15,4362.96 3517.52,4362.96 3529.42,4351.05 R42.1@3529.42,4350 ; U10.9@3683.78,4416.18 3665.04,4416.18 3657.73,4423.49 3647.94,4423.49 v1(3644.69,4426.75) 3645.67,4426.75 3659.97,4441.05 3683.06,4441.05 U10.8@3683.78,4441.77
  Bottom Layer w10: v1(3496.5,4370) 3587.94,4370 v1(3644.69,4426.75)
NetR43_2: R43.2 U10.10 | length 586.4
  Top Layer w10: U10.10@3683.78,4390.59 3749.41,4390.59 3885,4255 4167.4,4255 4195.51,4283.11 R43.2@4195.51,4290
NetR45_1: R45.1 U11.6 U11.7 | length 490.8
  Top Layer w10: R45.1@3534.42,3800 3534.42,3801.05 3566.32,3832.96 3697.32,3832.96 3888.5,3641.77 U11.7@3906.22,3641.77 U11.6@3906.22,3616.18
NetR50_2: R50.2 U11.5 | length 134.4
  Top Layer w10: U11.5@3906.22,3590.59 3906.94,3591.31 3930.03,3591.31 3954.2,3615.49 3954.2,3622.67 3975.4,3643.86 3980.24,3643.86 3999.49,3663.11 R50.2@3999.49,3670
NetR54_1: R54.1 U11.8 U11.9 | length 307.3
  Top Layer w10: v1(3496.5,3570) 3499.75,3566.75 3517.67,3566.75 3521.47,3562.96 3522.52,3562.96 3534.42,3551.05 R54.1@3534.42,3550 ; U11.9@3683.78,3616.18 3665.04,3616.18 3657.73,3623.49 3647.94,3623.49 v1(3644.69,3626.75) 3645.67,3626.75 3659.97,3641.05 3683.06,3641.05 U11.8@3683.78,3641.77
  Bottom Layer w10: v1(3496.5,3570) 3587.94,3570 v1(3644.69,3626.75)
NetR55_2: R55.2 U11.10 | length 590.6
  Top Layer w10: U11.10@3683.78,3590.59 3755.18,3590.59 3895.78,3450 4162.4,3450 4195.51,3483.11 R55.2@4195.51,3490
NetR58_2: R58.2 U12.4 | length 156.3
  Top Layer w15: U12.4@3102.4,2863.23 3102.4,2872.09 3184.86,2954.54 3200.92,2954.54 R58.2@3211.38,2965
NetR61_2: R61.2 U12.3 | length 303.2
  Top Layer w15: U12.3@3102.4,2766.77 3102.4,2672.6 3146.05,2628.95 3248.47,2628.95 3257.26,2637.74 3257.26,2654.54 3267.72,2665 R61.2@3268.62,2665
NetR62_2: R62.2 U15.4 | length 156.3
  Top Layer w10: U15.4@3102.4,2263.23 3102.4,2272.09 3182.36,2352.04 3198.42,2352.04 R62.2@3211.38,2365
NetR65_2: R65.2 U15.3 | length 281.8
  Top Layer w10: U15.3@3102.4,2166.77 3102.4,2092.6 3165,2030 3234.41,2030 3245.24,2040.83 3245.24,2042.52 3267.72,2065 R65.2@3268.62,2065
NetR66_2: R66.2 U17.4 | length 156.3
  Top Layer w10: U17.4@3102.4,1578.23 3102.4,1587.09 3182.36,1667.04 3198.42,1667.04 R66.2@3211.38,1680
NetR69_2: R69.2 U17.3 | length 300.6
  Top Layer w10: U17.3@3102.4,1481.77 3102.4,1372.6 3127.96,1347.04 3236.45,1347.04 3245.24,1355.83 3245.24,1357.52 3267.72,1380 R69.2@3268.62,1380
NetR70_2: R70.2 U20.4 | length 156.3
  Top Layer w10: U20.4@3102.4,978.23 3102.4,987.09 3111.18,995.87 3126.34,995.87 3210.47,1080 R70.2@3211.38,1080
NetR72_1: R72.1 R73.2 U21.6 | length 565.3
  Top Layer w10: R72.1@607.24,890 608.15,890 648.15,850 660.14,850 670.77,839.37 U21.6@692.91,839.37 692.91,857.91 800.46,965.46 969.84,965.46 990,945.31 990,927.72 952.28,890 R73.2@951.38,890 R73.2@938.42,902.96
NetR73_1: R73.1 R81.2 U21.2 | length 518.7
  Top Layer w10: U21.2@867.09,780.31 867.99,779.41 899.94,779.41 910,769.35 910,685.4 915.86,679.54 977.26,679.54 1007.72,710 R81.2@1008.62,710 1010.25,711.62 1036.62,711.62 1073.13,748.13 1073.13,867.78 1050.91,890 R73.1@1008.62,890
NetR75_1: R75.1 U21.7 | length 91.3
  Top Layer w10: R75.1@605.87,830 640.09,830 649.86,820.23 692.37,820.23 U21.7@692.91,819.68
NetR76_2: R76.2 U20.3 | length 280.2
  Top Layer w10: U20.3@3102.4,881.77 3102.4,817.48 3179.88,740 3229.41,740 3245.24,755.83 3245.24,757.52 3267.72,780 R76.2@3268.62,780
NetR80_2: R80.2 R81.1 U21.3 | length 156.7
  Top Layer w10: U21.3@867.09,800 920.47,800 950.47,770 R80.2@951.38,770 R81.1@951.38,710
NetR111_2: R111.2 R112.1 | length 89.8
  Bottom Layer w40: R112.1@4275.12,2365 R111.2@4364.88,2365
NetR112_2: R112.2 R113.1 | length 89.8
  Bottom Layer w40: R113.1@4075.12,2365 R112.2@4164.88,2365
NetR113_2: R113.2 R114.1 | length 89.8
  Bottom Layer w40: R114.1@3875.12,2365 R113.2@3964.88,2365
NetR114_2: R114.2 R115.1 | length 89.8
  Bottom Layer w40: R115.1@3675.12,2365 R114.2@3764.88,2365
NetR115_2: R115.2 R116.1 | length 89.8
  Bottom Layer w40: R116.1@3475.12,2365 R115.2@3564.88,2365
NetR117_2: R117.2 R118.1 | length 89.8
  Bottom Layer w40: R118.1@4275.12,2065 R117.2@4364.88,2065
NetR118_2: R118.2 R119.1 | length 89.8
  Bottom Layer w40: R119.1@4075.12,2065 R118.2@4164.88,2065
NetR119_2: R119.2 R120.1 | length 89.8
  Bottom Layer w40: R120.1@3875.12,2065 R119.2@3964.88,2065
NetR120_2: R120.2 R121.1 | length 89.8
  Bottom Layer w40: R121.1@3675.12,2065 R120.2@3764.88,2065
NetR121_2: R121.2 R122.1 | length 89.8
  Bottom Layer w40: R122.1@3475.12,2065 R121.2@3564.88,2065
NetR135_2: R135.2 R136.1 | length 89.8
  Bottom Layer w40: R136.1@4275.12,1080 R135.2@4364.88,1080
NetR136_2: R136.2 R137.1 | length 89.8
  Bottom Layer w40: R137.1@4075.12,1080 R136.2@4164.88,1080
NetR137_2: R137.2 R138.1 | length 89.8
  Bottom Layer w40: R138.1@3875.12,1080 R137.2@3964.88,1080
NetR138_2: R138.2 R139.1 | length 89.8
  Bottom Layer w40: R139.1@3675.12,1080 R138.2@3764.88,1080
NetR139_2: R139.2 R140.1 | length 89.8
  Bottom Layer w40: R140.1@3475.12,1080 R139.2@3564.88,1080
NetR142_2: R142.2 R143.1 | length 89.8
  Bottom Layer w40: R143.1@4275.12,780 R142.2@4364.88,780
NetR143_2: R143.2 R144.1 | length 89.8
  Bottom Layer w40: R144.1@4075.12,780 R143.2@4164.88,780
NetR144_2: R144.2 R145.1 | length 89.8
  Bottom Layer w40: R145.1@3875.12,780 R144.2@3964.88,780
NetR145_2: R145.2 R146.1 | length 93.9
  Bottom Layer w40: R146.1@3675.12,780 3680.12,785 3755,785 3760,780 R145.2@3764.88,780
NetR146_2: R146.2 R147.1 | length 89.8
  Bottom Layer w40: R147.1@3475.12,780 R146.2@3564.88,780
OUTA_FLT: U1.123 U2.3 | length 1201.8
  Top Layer w10: U1.123@2736.42,7203.28 2738.07,7204.92 2794.98,7204.92 v1(2796.63,7206.57) ; U2.3@3019.92,8178.39 3021.61,8176.69 3073.31,8176.69 v1(3075,8175)
  Bottom Layer w10: v1(2796.63,7206.57) v1(2796.63,7206.57) 3015,7425 3015,8115 v1(3075,8175)
OUTA_FLT_N: J2.8 L1.1 | length 1551.3
  Top Layer w10: L1.1@3555.55,8455 3795,8455 4500,7750 4744.09,7750 J2.8@4794.09,7700
OUTA_FLT_N_FILT: C1.2 L1.2 R1.1 U2.1 | length 569.1
  Top Layer w10: U2.1@3019.92,8229.57 3169.87,8229.57 3333.93,8393.62 C1.2@3370,8393.62 3372.95,8393.62 3389.91,8410.58 R1.1@3435,8410.58 3446.9,8422.48 3461.94,8422.48 3470.79,8431.33 3472.79,8431.33 3494.45,8453 L1.2@3494.45,8455
OUTA_FLT_P: J2.7 L2.1 | length 1414
  Top Layer w10: L2.1@3555.55,8365 3856.72,8365 4521.72,7700 J2.7@4694.09,7700
OUTA_FLT_P_FILT: C1.1 L2.2 R1.2 U2.2 | length 541.2
  Top Layer w10: U2.2@3019.92,8203.98 3173.98,8203.98 3276.5,8306.5 3327.17,8306.5 3367.05,8346.38 3431.96,8346.38 R1.2@3435,8349.42 3436.05,8349.42 3451.63,8365 L2.2@3494.45,8365
OUTA_HS: R83.1 U1.50 | length 1200.3
  Top Layer w10: v1(2580,5120) 2584.6,5120 2590.82,5113.78 U1.50@2657.68,5113.78
  Bottom Layer w10: v1(2580,5120) 2583.25,5116.75 2597.95,5116.75 2598.19,5116.5 2645.75,5116.5 2911.84,5382.59 2911.84,5563.91 3177.92,5830 3182.97,5830 3230,5877.03 R83.1@3230,5924.42
OUTA_HS_N: J2.4 U6.3 | length 2608.5
  Top Layer w10: U6.3@3260.08,6101.61 3261.53,6100.16 3315.95,6100.16 3319.03,6097.08 3347.44,6097.08 v1(3349.45,6095.06)
  Bottom Layer w10: v1(3349.45,6095.06) 3349.45,6189.45 3365,6205 3486.42,6205 3820,6538.58 3820,6806.72 4515,7501.72 4515,7692.62 4667.89,7845.51 4703.97,7845.51 4748.69,7890.24 4784.33,7890.24 J2.4@4794.09,7900
OUTA_HS_P: J2.3 U6.2 | length 2539
  Top Layer w10: U6.2@3260.08,6076.02 3314.38,6076.02 3321.82,6068.58 v1(3323.61,6068.58)
  Bottom Layer w10: v1(3323.61,6068.58) 3320.95,6071.24 3320.95,6189.24 3356.72,6225 3478.14,6225 3800,6546.86 3800,6815 4495,7510 4495,7700.91 J2.3@4694.09,7900
OUTA_LEN: J2.13 U3.15 | length 2010.5
  Top Layer w10: U3.15@3252.2,7627.2 3203.06,7627.2 3190,7614.14 3190,7507.21 3232.21,7465 3730,7465 3965,7230 4710,7230 4739.61,7259.61 4739.61,7354.49 J2.13@4694.09,7400
OUTA_LEN_CTRL: U1.145 U3.5 | length 706.1
  Top Layer w10: U1.145@2736.42,7549.73 2741.26,7544.89 2775.11,7544.89 2895,7425 3064.85,7425 3126.42,7486.56 3126.42,7608.58 3082.2,7652.8 U3.5@3027.8,7652.8
OUTA_LS: R84.1 U1.52 | length 1082.9
  Top Layer w10: v1(2610,5145) 2610.14,5145.14 2657.54,5145.14 U1.52@2657.68,5145.28
  Bottom Layer w10: v1(2610,5145) 2649.5,5145 2890.62,5386.13 2890.62,5574.06 3128.5,5811.93 3128.5,5883.97 3168.95,5924.42 R84.1@3170,5924.42
OUTA_LS_N: J2.6 U6.5 | length 2496.7
  Top Layer w10: U6.5@3260.08,6152.8 3261.37,6151.5 3374.2,6151.5 3382.14,6143.56 3386.74,6143.56 v1(3412.5,6117.81)
  Bottom Layer w10: v1(3412.5,6117.81) 3412.5,6121.95 3455.55,6165 3510,6165 3860,6515 3860,6790.15 4565,7495.15 4565,7645 4665.51,7745.51 4703.97,7745.51 4748.69,7790.24 4784.33,7790.24 J2.6@4794.09,7800
OUTA_LS_P: J2.5 U6.6 | length 2381.8
  Top Layer w10: U6.6@3260.08,6178.39 3260.89,6179.19 3387.99,6179.19 3406.44,6160.75 v1(3409.86,6160.75)
  Bottom Layer w10: v1(3409.86,6160.75) 3434.11,6185 3500.31,6185 3840,6524.69 3840,6798.43 4540,7498.43 4540,7670 4600.12,7730.12 4621.83,7730.12 4691.72,7800 J2.5@4694.09,7800
OUTA_NTC: U1.62 U2.13 | length 3293.4
  Top Layer w10: v1(2575,5467.85) 2578.25,5464.6 2599.16,5464.6 2625.86,5437.89 2631.79,5437.89 2640.94,5428.74 U1.62@2657.68,5428.74 ; v1(3205,8157) 3207.47,8154.53 3258.35,8154.53 U2.13@3260.08,8152.8
  Bottom Layer w10: v1(2575,5467.85) 2575,5550 2747.5,5722.5 2747.5,7222.5 2935,7410 2935,8113.28 3045.22,8223.5 3136.5,8223.5 3180,8180 3182,8180 v1(3205,8157)
OUTA_NTC_N: J2.10 L3.1 | length 1517.6
  Top Layer w10: L3.1@3556.09,8275 3918.28,8275 4543.28,7650 4708.46,7650 4748.69,7609.76 4784.33,7609.76 J2.10@4794.09,7600
OUTA_NTC_N_FILT: C3.2 L3.2 R2.1 U2.15 | length 292.1
  Top Layer w10: U2.15@3260.08,8203.98 3261.81,8205.71 3296.65,8205.71 3321.36,8230.42 3321.36,8251.43 3353.79,8283.86 3360.24,8283.86 C3.2@3370,8293.62 3431.96,8293.62 R2.1@3435,8290.58 3479.42,8290.58 L3.2@3495,8275
OUTA_NTC_P: J2.9 L4.1 | length 1380.3
  Top Layer w10: L4.1@3556.09,8185 3980,8185 4565,7600 J2.9@4694.09,7600
OUTA_NTC_P_FILT: C3.1 L4.2 R2.2 U2.14 | length 291.4
  Top Layer w10: U2.14@3260.08,8178.39 3302.01,8178.39 3357.28,8233.66 3357.28,8236.61 3367.05,8246.38 C3.1@3370,8246.38 3416.99,8246.38 3433.95,8229.42 R2.2@3435,8229.42 3446.9,8217.52 3464.49,8217.52 3495,8187 L4.2@3495,8185
OUTA_OCEN: J2.15 U3.14 | length 1712.3
  Top Layer w10: U3.14@3235,7598.9 3223.52,7598.9 3213.58,7588.96 3213.58,7511.91 3235.49,7490 3733.28,7490 3973.28,7250 4644.09,7250 J2.15@4694.09,7300
OUTA_OCEN_CTRL: U1.147 U3.6 | length 635.4
  Top Layer w10: U1.147@2736.42,7581.23 2741.26,7576.39 2778.61,7576.39 2910,7445 3056.57,7445 3106.42,7494.85 3106.42,7588.58 3067.8,7627.2 U3.6@3027.8,7627.2
OUTA_PSDIS: J2.11 U3.16 | length 2370.8
  Top Layer w10: U3.16@3252.2,7652.8 3200.37,7652.8 3170,7622.43 3170,7498.92 3228.92,7440 3725,7440 3955,7210 4796.74,7210 4840,7253.26 4840,7418.46 4803.97,7454.49 4739.61,7454.49 J2.11@4694.09,7500
OUTA_PSDIS_CTRL: U1.143 U3.4 | length 772.9
  Top Layer w10: U1.143@2736.42,7518.24 2741.26,7513.39 2773.3,7513.39 2881.69,7405 3073.14,7405 3150,7481.86 3150,7613.28 3084.9,7678.39 U3.4@3027.8,7678.39
OUTB_FLT: U1.124 U2.11 | length 1485.6
  Top Layer w10: U1.124@2657.68,7203.28 2653.26,7198.86 2624.46,7198.86 2618.6,7193 2618.6,7156.76 2645.36,7130 2795.64,7130 2805.64,7120 v1(2810,7120) ; v1(3205,8100) 3205.81,8100.81 3259.27,8100.81 U2.11@3260.08,8101.61
  Bottom Layer w10: v1(2810,7120) 2810,7179.64 2825.13,7194.77 2825.13,7195.13 3035,7405 3035,7825 3205,7995 v1(3205,8100)
OUTB_FLT_N: J1.8 L6.1 | length 742.7
  Top Layer w10: L6.1@3556.09,8005 3568.1,7993 3706.09,7993 3876.04,7823.05 3876.04,7753.69 3975.24,7654.49 4048.58,7654.49 J1.8@4094.09,7700
OUTB_FLT_N_FILT: C4.2 L6.2 R3.1 U2.9 | length 274.7
  Top Layer w10: U2.9@3260.08,8050.43 3269.57,8050.43 3270,8050 3283.15,8050 3311.93,8021.22 3311.93,8011.73 3337.28,7986.38 C4.2@3370,7986.38 3431.96,7986.38 R3.1@3435,7989.42 3479.42,7989.42 L6.2@3495,8005
OUTB_FLT_P: J1.7 L5.1 | length 652.8
  Top Layer w10: L5.1@3555,8095 3555,8093 3576.66,8071.33 3578.67,8071.33 3611.33,8038.67 3738.97,8038.67 3861.65,7915.98 3861.65,7867.73 3984.33,7745.05 3984.33,7709.76 J1.7@3994.09,7700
